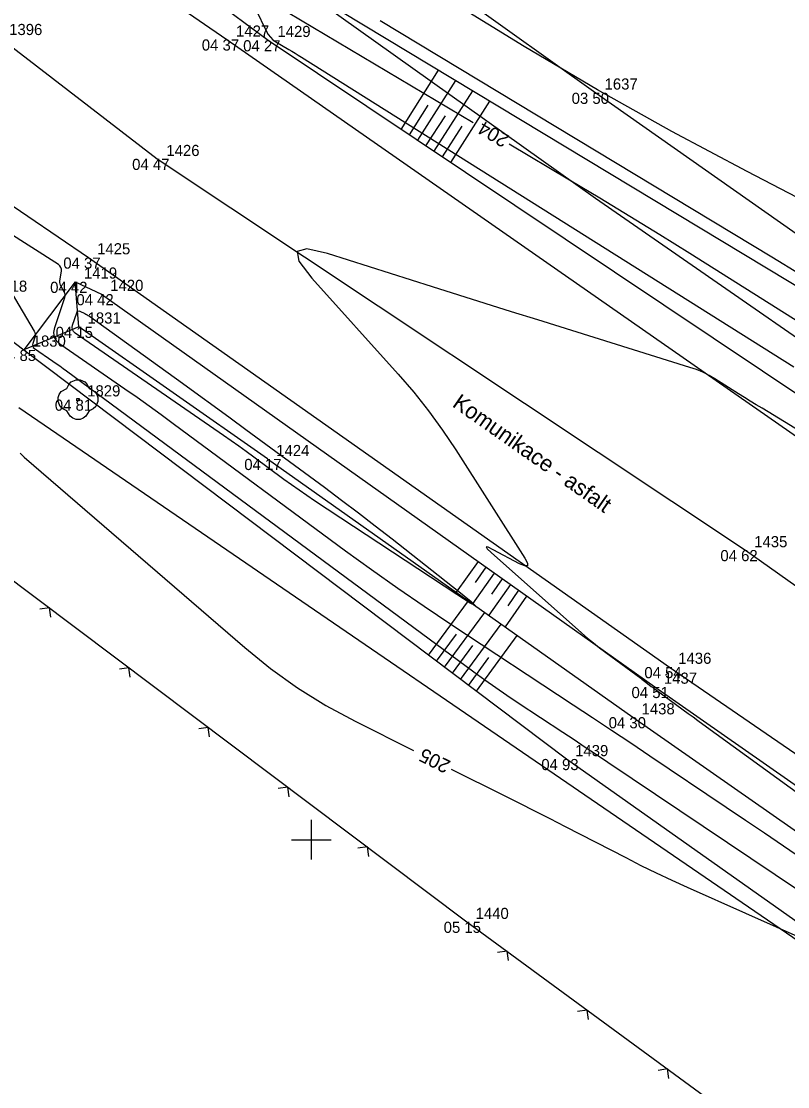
# Model space of a CAD drawing. Extents: x -711234 to -710007, y -1026313 to -1025448.
# Drawn here: x -710507.29 to -710488.03, y -1025606.2 to -1025579.43 of the extents above; entities that cross this region are included whole.
import ezdxf

# ---------------------------------------------------------------- set-up
doc = ezdxf.new("R2010")
doc.units = 0
for name, color, linetype in [('Ex_Contour Labels', 7, 'Continuous'), ('Ex_Major Contours', 7, 'Continuous'), ('Ex_Minor Contours', 7, 'Continuous'), ('Z_body', 7, 'Continuous'), ('Z_body_cisla', 7, 'Continuous'), ('Z_body_vysky_redukovane', 7, 'Continuous'), ('Z_hektometricka_sit', 7, 'Continuous'), ('Z_hrany_paty', 7, 'Continuous'), ('Z_katastr_hranice', 7, 'Continuous'), ('Z_komunikace', 7, 'Continuous'), ('Z_komunikace_osa', 7, 'Continuous'), ('Z_ploty', 7, 'Continuous'), ('Z_ploty_znacky', 7, 'Continuous'), ('Z_pole_rozhranni', 7, 'Continuous'), ('Z_popisy', 7, 'Continuous'), ('Z_technicke_srafy', 7, 'Continuous'), ('Z_zelen_jednotliva', 7, 'Continuous')]:
    doc.layers.add(name, color=color, linetype=linetype)

# ---------------------------------------------------------------- blocks, each defined once
blk = doc.blocks.new('POINT_DISPLAY')
blk.add_line((0, 0), (0, 0))
blk = doc.blocks.new('Z24')
for p, q in [((-0.42, 0.2), (-0.28, 0.28)), ((-0.28, 0.28), (-0.23, 0.38)), ((-0.23, 0.38), (-0.17, 0.45)), ((-0.17, 0.45), (-0.05, 0.5)), ((-0.05, 0.5), (0.05, 0.5)), ((0.05, 0.5), (0.17, 0.45)), ((0.17, 0.45), (0.23, 0.38)), ((0.23, 0.38), (0.28, 0.28)), ((0.28, 0.28), (0.42, 0.2)), ((-0.5, 0.05), (-0.47, 0.13)), ((-0.5, -0.05), (-0.5, 0.05)), ((-0.47, 0.13), (-0.42, 0.2)), ((-0.03, -0.03), (-0.03, 0.03)), ((-0.03, 0.03), (0.03, 0.03)), ((0.03, 0.03), (0.03, -0.03)), ((0.42, 0.2), (0.47, 0.13)), ((0.47, 0.13), (0.5, 0.05)), ((0.5, 0.05), (0.5, -0.05)), ((-0.45, -0.17), (-0.5, -0.05)), ((-0.38, -0.23), (-0.45, -0.17)), ((-0.28, -0.28), (-0.38, -0.23)), ((0.03, -0.03), (-0.03, -0.03)), ((0.38, -0.23), (0.28, -0.28)), ((0.45, -0.17), (0.38, -0.23)), ((0.5, -0.05), (0.45, -0.17)), ((-0.2, -0.42), (-0.28, -0.28)), ((-0.13, -0.47), (-0.2, -0.42)), ((-0.05, -0.5), (-0.13, -0.47)), ((0.05, -0.5), (-0.05, -0.5)), ((0.13, -0.47), (0.05, -0.5)), ((0.2, -0.42), (0.13, -0.47)), ((0.28, -0.28), (0.2, -0.42))]:
    blk.add_line(p, q)
blk = doc.blocks.new('Z212')
for p, q in [((-0.17, 0.17), (0, 0)), ((0, 0), (0.17, 0.17))]:
    blk.add_line(p, q)

msp = doc.modelspace()

# ---------------------------------------------------------------- linework, layer by layer
at = {"layer": 'Ex_Major Contours'}
for points in [[(-710500.578, -1025579.211), (-710495.929, -1025581.975)], [(-710495.027, -1025582.511), (-710493.509, -1025583.414), (-710492.75, -1025583.868), (-710491.994, -1025584.327), (-710491.24, -1025584.791), (-710490.49, -1025585.26), (-710487.494, -1025587.143)], [(-710507.317, -1025590.29), (-710507.211, -1025590.388), (-710501.672, -1025595.173), (-710501.022, -1025595.701), (-710500.342, -1025596.185), (-710499.634, -1025596.625), (-710498.897, -1025597.022), (-710497.428, -1025597.754)], [(-710496.488, -1025598.223), (-710495.153, -1025598.889), (-710494.77, -1025599.081), (-710494.387, -1025599.274), (-710494.005, -1025599.468), (-710493.623, -1025599.664), (-710492.098, -1025600.449), (-710491.716, -1025600.643), (-710491.33, -1025600.831), (-710490.943, -1025601.014), (-710490.553, -1025601.192), (-710487.623, -1025602.502)]]:
    msp.add_lwpolyline(points, dxfattribs=at)
at = {"layer": 'Ex_Minor Contours'}
for points in [[(-710474.069, -1025590.994), (-710489.047, -1025583.207), (-710490.938, -1025582.2), (-710492.806, -1025581.154), (-710494.653, -1025580.07), (-710496.478, -1025578.948)], [(-710501.4, -1025579.118), (-710501.128, -1025579.688), (-710501.082, -1025579.767), (-710501.027, -1025579.837), (-710500.962, -1025579.899), (-710500.887, -1025579.951), (-710500.567, -1025580.141), (-710500.487, -1025580.189), (-710500.407, -1025580.238), (-710500.328, -1025580.286), (-710500.249, -1025580.336), (-710487.871, -1025588.117)], [(-710487.714, -1025585.794), (-710488.428, -1025585.358), (-710498.27, -1025579.421)], [(-710487.656, -1025600.487), (-710488.134, -1025600.161), (-710488.612, -1025599.836), (-710489.091, -1025599.512), (-710489.571, -1025599.189), (-710491.49, -1025597.899), (-710491.971, -1025597.577), (-710492.452, -1025597.256), (-710492.933, -1025596.936), (-710493.416, -1025596.617), (-710496.492, -1025594.591), (-710497.162, -1025594.143), (-710497.827, -1025593.686), (-710498.485, -1025593.22), (-710499.137, -1025592.745), (-710503.469, -1025589.545), (-710503.77, -1025589.324), (-710504.073, -1025589.105), (-710504.378, -1025588.889), (-710504.685, -1025588.675), (-710506.292, -1025587.565), (-710506.39, -1025587.475), (-710506.448, -1025587.372), (-710506.464, -1025587.255), (-710506.44, -1025587.125), (-710506.194, -1025586.371), (-710506.186, -1025586.335), (-710506.186, -1025586.3), (-710506.193, -1025586.266), (-710506.209, -1025586.233), (-710506.286, -1025586.101), (-710506.302, -1025586.068), (-710506.312, -1025586.033), (-710506.316, -1025585.997), (-710506.314, -1025585.96), (-710506.278, -1025585.714), (-710506.277, -1025585.664), (-710506.289, -1025585.619), (-710506.315, -1025585.581), (-710506.354, -1025585.549), (-710509.134, -1025583.782)], [(-710487.695, -1025589.75), (-710488.671, -1025589.158), (-710488.82, -1025589.068), (-710488.969, -1025588.976), (-710489.117, -1025588.884), (-710489.265, -1025588.792), (-710489.856, -1025588.42), (-710490.006, -1025588.332), (-710490.161, -1025588.255), (-710490.321, -1025588.187), (-710490.485, -1025588.13), (-710494.308, -1025586.938), (-710494.969, -1025586.731), (-710495.63, -1025586.524), (-710496.29, -1025586.316), (-710496.951, -1025586.108), (-710499.593, -1025585.273), (-710500.113, -1025585.155), (-710500.352, -1025585.218), (-710500.31, -1025585.462), (-710499.988, -1025585.886), (-710497.817, -1025588.3), (-710497.426, -1025588.753), (-710497.054, -1025589.222), (-710496.702, -1025589.705), (-710496.37, -1025590.204), (-710494.636, -1025592.923), (-710494.569, -1025593.05), (-710494.568, -1025593.116), (-710494.634, -1025593.12), (-710494.766, -1025593.063), (-710495.426, -1025592.712), (-710495.553, -1025592.651), (-710495.604, -1025592.643), (-710495.579, -1025592.687), (-710495.477, -1025592.785), (-710493.207, -1025594.804), (-710493.059, -1025594.932), (-710492.909, -1025595.056), (-710492.756, -1025595.178), (-710492.6, -1025595.295), (-710491.723, -1025595.942), (-710491.69, -1025595.967), (-710491.657, -1025595.992), (-710491.624, -1025596.017), (-710491.591, -1025596.043), (-710491.461, -1025596.145), (-710491.429, -1025596.17), (-710491.396, -1025596.196), (-710491.363, -1025596.22), (-710491.329, -1025596.245), (-710490.655, -1025596.735), (-710490.531, -1025596.825), (-710490.408, -1025596.915), (-710490.284, -1025597.005), (-710490.161, -1025597.094), (-710480.618, -1025604.016)], [(-710507.54, -1025586.241), (-710506.962, -1025587.221), (-710506.945, -1025587.257), (-710506.937, -1025587.294), (-710506.937, -1025587.332), (-710506.946, -1025587.371), (-710506.997, -1025587.528), (-710507.004, -1025587.566), (-710506.999, -1025587.599), (-710506.983, -1025587.629), (-710506.955, -1025587.654), (-710506.496, -1025587.971), (-710506.408, -1025588.033), (-710506.321, -1025588.094), (-710506.234, -1025588.157), (-710506.148, -1025588.22), (-710495.912, -1025595.783), (-710495.639, -1025595.982), (-710495.363, -1025596.177), (-710495.085, -1025596.368), (-710494.805, -1025596.556), (-710493.677, -1025597.299), (-710493.395, -1025597.485), (-710493.114, -1025597.671), (-710492.833, -1025597.859), (-710492.552, -1025598.047), (-710485.952, -1025602.484)]]:
    msp.add_lwpolyline(points, dxfattribs=at)
msp.add_lwpolyline([(-710505.66, -1025586.793), (-710505.63, -1025586.809), (-710505.602, -1025586.827), (-710505.574, -1025586.846), (-710503.233, -1025588.53), (-710502.834, -1025588.818), (-710502.436, -1025589.108), (-710502.039, -1025589.398), (-710501.643, -1025589.689), (-710499.671, -1025591.144), (-710499.242, -1025591.463), (-710498.816, -1025591.785), (-710498.392, -1025592.111), (-710497.971, -1025592.44), (-710496.291, -1025593.762), (-710495.979, -1025594.015), (-710495.884, -1025594.111), (-710496.005, -1025594.052), (-710496.344, -1025593.836), (-710499.917, -1025591.482), (-710500.113, -1025591.352), (-710500.306, -1025591.218), (-710500.497, -1025591.083), (-710500.687, -1025590.945), (-710501.442, -1025590.387), (-710501.632, -1025590.248), (-710501.822, -1025590.111), (-710502.014, -1025589.975), (-710502.206, -1025589.841), (-710505.929, -1025587.268), (-710505.974, -1025587.227), (-710506, -1025587.18), (-710506.007, -1025587.127), (-710505.996, -1025587.068), (-710505.894, -1025586.756), (-710505.881, -1025586.729), (-710505.863, -1025586.715), (-710505.84, -1025586.712), (-710505.812, -1025586.72), (-710505.69, -1025586.778)], close=True, dxfattribs=at)
at = {"layer": 'Z_hektometricka_sit'}
for p, q in [((-710500, -1025599.5), (-710500, -1025600.5)), ((-710500.5, -1025600), (-710499.5, -1025600))]:
    msp.add_line(p, q, dxfattribs=at)
at = {"layer": 'Z_hrany_paty'}
for p, q in [((-710505.57, -1025576.58), (-710501.08, -1025579.91)), ((-710500.66, -1025578.33), (-710485.59, -1025587.42)), ((-710501.08, -1025579.91), (-710486.83, -1025589.45)), ((-710513.25, -1025583.14), (-710507.22, -1025587.69)), ((-710505.93, -1025585.98), (-710507.22, -1025587.69)), ((-710505.93, -1025585.98), (-710505.27, -1025586.29)), ((-710505.84, -1025587.11), (-710505.93, -1025585.98)), ((-710505.27, -1025586.29), (-710491.37, -1025596.16)), ((-710505.84, -1025587.11), (-710507.22, -1025587.69)), ((-710501.1, -1025590.43), (-710505.84, -1025587.11)), ((-710507.22, -1025587.69), (-710493.59, -1025597.97)), ((-710501.1, -1025590.43), (-710491.92, -1025596.92)), ((-710491.37, -1025596.16), (-710477.02, -1025606.17)), ((-710491.92, -1025596.92), (-710477.9, -1025606.73)), ((-710493.59, -1025597.97), (-710479.18, -1025608.14))]:
    msp.add_line(p, q, dxfattribs=at)
at = {"layer": 'Z_katastr_hranice'}
msp.add_line((-710463.69, -1025619.02), (-710507.35, -1025589.15), dxfattribs=at)
msp.add_lwpolyline([(-710600.21, -1025504.82), (-710580.45, -1025521.54), (-710492.86, -1025583.88), (-710429.93, -1025627.5), (-710391.58, -1025654.85), (-710379.57, -1025662.83), (-710367.07, -1025673.36), (-710347.9, -1025691.71), (-710333.8, -1025705.97), (-710271.15, -1025774.38), (-710237.36, -1025811.14)], dxfattribs=at)
at = {"layer": 'Z_komunikace'}
for p, q in [((-710505.98, -1025577.22), (-710502.12, -1025579.89)), ((-710502.12, -1025579.89), (-710487.39, -1025590.16)), ((-710510.11, -1025582.3), (-710505.6, -1025585.37)), ((-710505.6, -1025585.37), (-710491, -1025595.66)), ((-710491, -1025595.66), (-710476.72, -1025605.47))]:
    msp.add_line(p, q, dxfattribs=at)
at = {"layer": 'Z_komunikace_osa'}
for p, q in [((-710507.82, -1025579.85), (-710503.87, -1025582.89)), ((-710503.87, -1025582.89), (-710489.09, -1025592.72)), ((-710489.09, -1025592.72), (-710474.21, -1025603.35))]:
    msp.add_line(p, q, dxfattribs=at)
at = {"layer": 'Z_ploty'}
for p, q in [((-710509.58, -1025591.92), (-710496.09, -1025602.06)), ((-710496.09, -1025602.06), (-710482.64, -1025611.92))]:
    msp.add_line(p, q, dxfattribs=at)
at = {"layer": 'Z_pole_rozhranni'}
for p, q in [((-710510.22, -1025568.84), (-710492.85, -1025581.23)), ((-710492.85, -1025581.23), (-710474.49, -1025594.13))]:
    msp.add_line(p, q, dxfattribs=at)
at = {"layer": 'Z_technicke_srafy'}
for p, q in [((-710497.74, -1025582.15), (-710496.8, -1025580.66)), ((-710497.32, -1025582.42), (-710496.37, -1025580.92)), ((-710496.91, -1025582.7), (-710495.94, -1025581.18)), ((-710497.53, -1025582.29), (-710497.06, -1025581.54)), ((-710496.49, -1025582.98), (-710495.51, -1025581.44)), ((-710497.12, -1025582.56), (-710496.63, -1025581.81)), ((-710496.7, -1025582.84), (-710496.21, -1025582.07)), ((-710495.81, -1025593.01), (-710496.36, -1025593.78)), ((-710495.4, -1025593.3), (-710495.95, -1025594.07)), ((-710495.61, -1025593.15), (-710495.88, -1025593.54)), ((-710494.99, -1025593.59), (-710495.54, -1025594.36)), ((-710495.2, -1025593.44), (-710495.47, -1025593.83)), ((-710494.59, -1025593.88), (-710495.13, -1025594.65)), ((-710494.79, -1025593.73), (-710495.06, -1025594.12)), ((-710497.05, -1025595.36), (-710496.05, -1025594)), ((-710496.65, -1025595.66), (-710495.64, -1025594.29)), ((-710496.25, -1025595.97), (-710495.23, -1025594.58)), ((-710496.85, -1025595.51), (-710496.35, -1025594.83)), ((-710495.85, -1025596.27), (-710494.83, -1025594.87)), ((-710496.45, -1025595.81), (-710495.94, -1025595.12)), ((-710496.05, -1025596.12), (-710495.54, -1025595.42))]:
    msp.add_line(p, q, dxfattribs=at)

# ---------------------------------------------------------------- block references
at = {"layer": 'Z_body'}
for p in [(-710502.12, -1025579.89), (-710501.08, -1025579.91), (-710492.85, -1025581.23), (-710503.87, -1025582.89), (-710505.6, -1025585.37), (-710505.93, -1025585.98), (-710505.27, -1025586.29), (-710505.84, -1025587.11), (-710507.22, -1025587.69), (-710505.86, -1025588.94), (-710501.1, -1025590.43), (-710489.09, -1025592.72), (-710491, -1025595.66), (-710491.37, -1025596.16), (-710491.92, -1025596.92), (-710493.59, -1025597.97), (-710496.09, -1025602.06)]:
    msp.add_blockref('POINT_DISPLAY', p, dxfattribs=at)
at = {"layer": 'Z_ploty_znacky'}
for p, rotation in [((-710506.58, -1025594.17), 143.1), ((-710504.58, -1025595.68), 143.1), ((-710502.59, -1025597.18), 143.1), ((-710500.59, -1025598.68), 143.1), ((-710498.59, -1025600.18), 143.1), ((-710495.08, -1025602.8), 143.8), ((-710493.07, -1025604.28), 143.8), ((-710491.05, -1025605.76), 143.8)]:
    msp.add_blockref('Z212', p, dxfattribs=dict(at, rotation=rotation))
at = {"layer": 'Z_zelen_jednotliva'}
msp.add_blockref('Z24', (-710505.86, -1025588.94), dxfattribs=at)

# ---------------------------------------------------------------- texts
at = {"layer": 'Ex_Contour Labels'}
for s, rotation, p in [('204', 149.2679, (-710495, -1025582.324)), ('205', 153.4946, (-710496.475, -1025598.034))]:
    msp.add_text(s, height=0.35, rotation=rotation, dxfattribs=at).set_placement(p)
at = {"layer": 'Z_body_cisla'}
for s, p in [('1396', (-710507.59, -1025579.78)), ('1427', (-710501.89, -1025579.82)), ('1429', (-710500.85, -1025579.83)), ('1637', (-710492.63, -1025581.15)), ('1426', (-710503.64, -1025582.82)), ('1425', (-710505.38, -1025585.29)), ('1419', (-710505.71, -1025585.9)), ('1418', (-710507.97, -1025586.23)), ('1420', (-710505.05, -1025586.21)), ('1831', (-710505.62, -1025587.03)), ('1830', (-710507, -1025587.61)), ('1829', (-710505.63, -1025588.86)), ('1424', (-710500.88, -1025590.36)), ('1435', (-710488.87, -1025592.65)), ('1436', (-710490.78, -1025595.58)), ('1437', (-710491.14, -1025596.08)), ('1438', (-710491.7, -1025596.85)), ('1439', (-710493.37, -1025597.9)), ('1440', (-710495.87, -1025601.99))]:
    msp.add_text(s, height=0.28, dxfattribs=at).set_placement(p)
at = {"layer": 'Z_body_vysky_redukovane'}
for s, p in [('04 37', (-710502.75, -1025580.17)), ('04 27', (-710501.71, -1025580.19)), ('03 50', (-710493.457, -1025581.51)), ('04 47', (-710504.5, -1025583.17)), ('04 37', (-710506.23, -1025585.65)), ('04 42', (-710506.56, -1025586.26)), ('04 42', (-710505.9, -1025586.57)), ('04 15', (-710506.423, -1025587.39)), ('04 85', (-710507.85, -1025587.97)), ('04 81', (-710506.443, -1025589.22)), ('04 17', (-710501.683, -1025590.71)), ('04 62', (-710489.72, -1025593)), ('04 54', (-710491.63, -1025595.94)), ('04 51', (-710491.953, -1025596.44)), ('04 30', (-710492.527, -1025597.2)), ('04 93', (-710494.22, -1025598.25)), ('05 15', (-710496.673, -1025602.34))]:
    msp.add_text(s, height=0.28, dxfattribs=at).set_placement(p)
at = {"layer": 'Z_popisy'}
msp.add_text('Komunikace - asfalt', height=0.4, rotation=324.9, dxfattribs=at).set_placement((-710496.48, -1025589.1))

doc.saveas('drawing.dxf')
